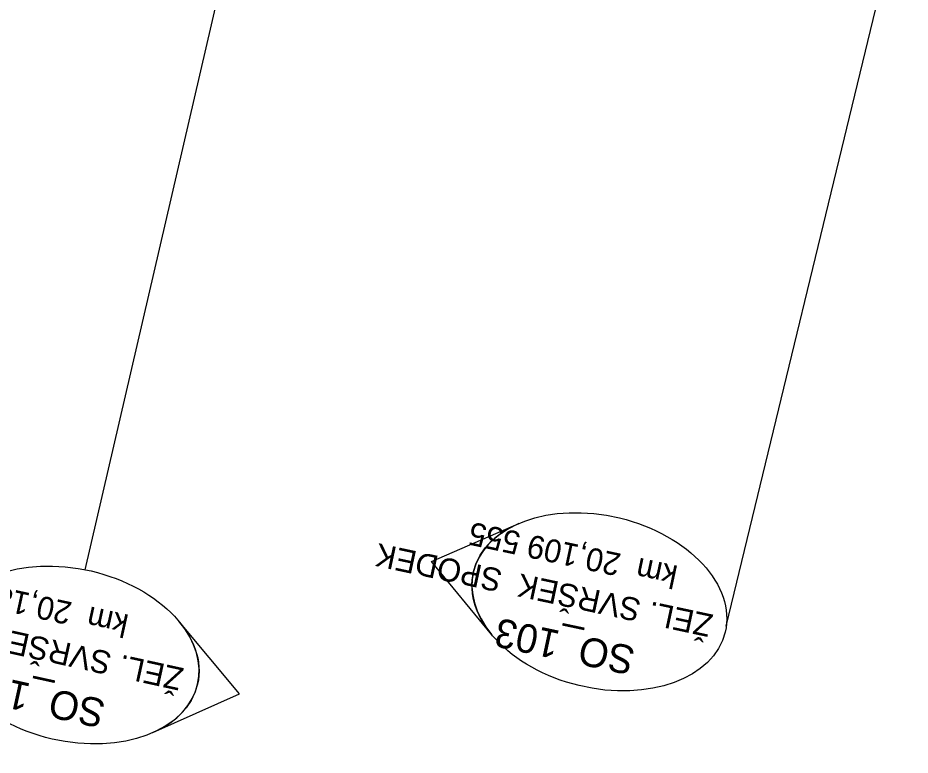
# Model space of a CAD drawing. Extents: x -748344 to -743169, y -1131966 to -1127091.
# Drawn here: x -747617.2 to -747539.7, y -1131796.3 to -1131732.2 of the extents above; entities that cross this region are included whole.
import ezdxf

# ---------------------------------------------------------------- set-up
doc = ezdxf.new("R2010")
doc.units = 0
for name, color, linetype in [('_Násyp', 7, 'Continuous'), ('bublina_fialová_čára_tenká', 7, 'Continuous'), ('bublina_růžová_230_čára_tučná', 7, 'Continuous')]:
    doc.layers.add(name, color=color, linetype=linetype)

msp = doc.modelspace()

# ---------------------------------------------------------------- linework, layer by layer
at = {"layer": 'bublina_fialová_čára_tenká'}
for p, q in [((-747611.38, -1131780.164), (-747594.166, -1131705.802)), ((-747555.646, -1131785.08), (-747539.653, -1131718.994))]:
    msp.add_line(p, q, dxfattribs=at)
at = {"layer": 'bublina_růžová_230_čára_tučná'}
for p, q in [((-747581.26, -1131779.435), (-747573.692, -1131776.14)), ((-747581.26, -1131779.435), (-747573.692, -1131776.14)), ((-747576.025, -1131785.818), (-747581.26, -1131779.435)), ((-747576.025, -1131785.818), (-747581.26, -1131779.435)), ((-747597.962, -1131790.966), (-747603.253, -1131784.63)), ((-747597.962, -1131790.966), (-747603.253, -1131784.63)), ((-747605.501, -1131794.327), (-747597.962, -1131790.966)), ((-747605.501, -1131794.327), (-747597.962, -1131790.966))]:
    msp.add_line(p, q, dxfattribs=at)
for centre, major_axis in [((-747566.678, -1131782.951), (10.937, -2.637)), ((-747612.575, -1131787.578), (-10.959, 2.541))]:
    msp.add_ellipse(centre, major_axis=major_axis, ratio=0.666667, dxfattribs=at)
for centre, major_axis in [((-747566.678, -1131782.951), (-10.938, 2.637)), ((-747612.575, -1131787.578), (10.961, -2.541))]:
    msp.add_ellipse(centre, major_axis=major_axis, ratio=0.666473, start_param=5.557317, end_param=7.009053, dxfattribs=at)

# ---------------------------------------------------------------- texts
at = {"layer": '_Násyp'}
for s, height, rotation, p in [('km  20,109 555', 2, 167.93786, (-747559.752, -1131779.847)), ('ŽEL. SVRŠEK  SPODEK', 2, 167.93786, (-747556.694, -1131784.087)), ('km  20,180', 2, 167.6146, (-747607.497, -1131784.104)), ('ŽEL. SVRŠEK  SPODEK', 2, 167.6146, (-747602.73, -1131788.743)), ('SO_103', 2.5, 167.93786, (-747563.434, -1131786.904)), ('SO_103', 2.5, 167.6146, (-747609.486, -1131791.521))]:
    msp.add_text(s, height=height, rotation=rotation, dxfattribs=at).set_placement(p)

doc.saveas('drawing.dxf')
